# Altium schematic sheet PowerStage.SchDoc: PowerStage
size A2; Date: Not shown in title block; ApprovedBy: Not shown in title block; CheckedBy: Not shown in title block; Author: Not shown in title block; CompanyName: TEXAS INSTRUMENTS; DrawnBy: Hely Zhang; Engineer: Hely Zhang; Organization: Not shown in title block; Address1: Not shown in title block; Address2: Not shown in title block; Address3: Not shown in title block; Address4: Not shown in title block; DocumentNumber: 3; Revision: Use project parameter SCH_Rev; SheetNumber: 3; SheetTotal: 6; PageSetup: Record=PageOptions¦CenterHorizontal=True¦CenterVertical=True¦PrintScale=1.00¦XCorrection=1.00¦YCorrection=1.00¦PrintKind=0¦BorderSize=5000000¦LeftOffset=0¦BottomOffset=0¦Orientation=2¦PaperLength=1000¦PaperWidth=1000¦Scale=100¦PaperSource=15¦PrintQuality=600¦MediaType=1¦DitherType=10¦PaperKind=Letter¦PrintScaleMode=1
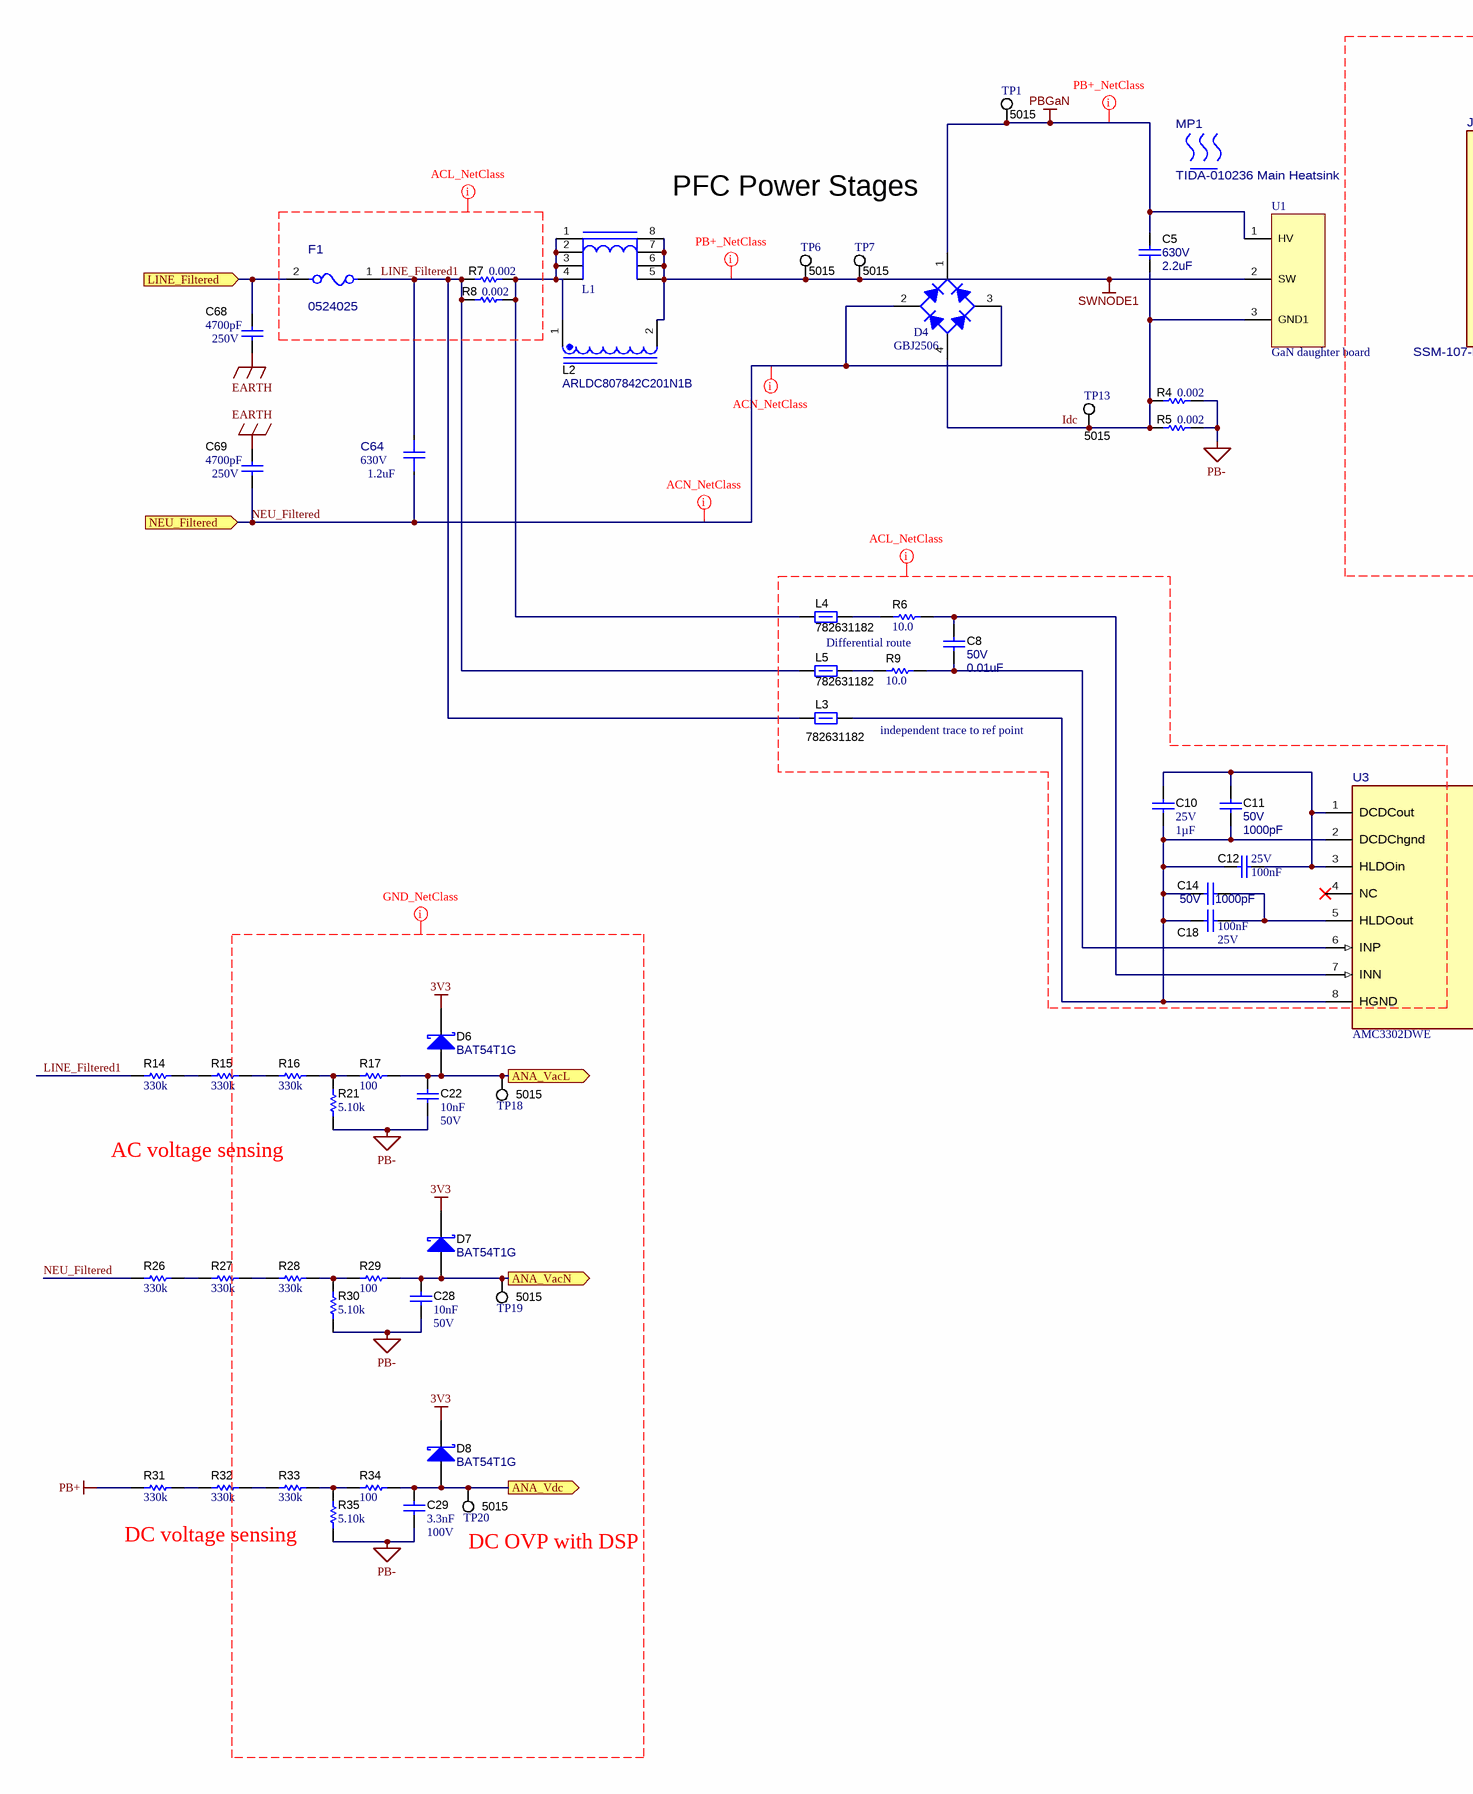
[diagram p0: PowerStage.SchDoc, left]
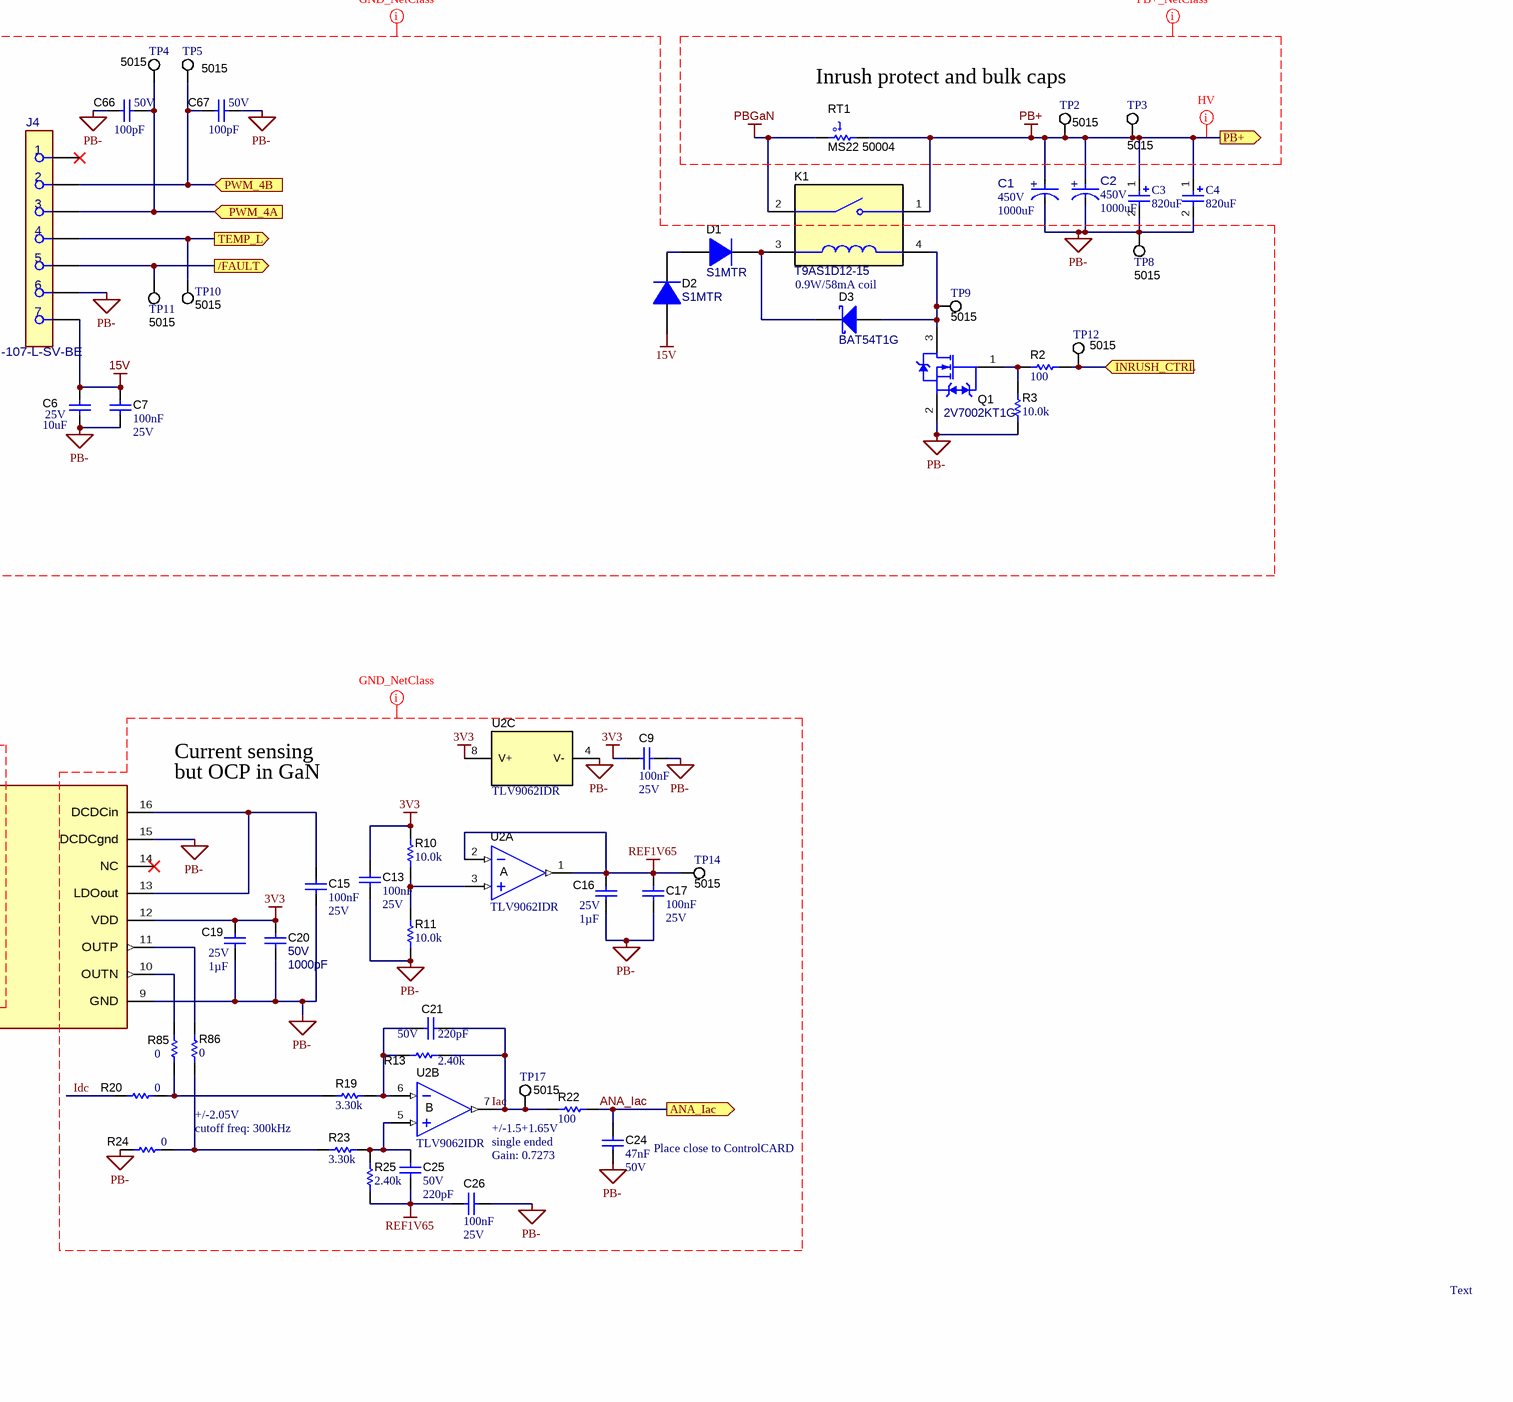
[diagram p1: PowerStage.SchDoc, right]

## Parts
C1  VDC_V: 450V  ValueDisplayed: 1000uF  [FP-S861021486045_RADIAL-MFG]  (hidden comment: S861021486045)
C2  VDC_V: 450V  ValueDisplayed: 1000uF  [FP-S861021486045_RADIAL-MFG]  (hidden comment: S861021486045)
C3  820uF  [Cap_35x60mm_Snap in]
C4  820uF  [Cap_35x60mm_Snap in]
C5  VDC_V: 630V  ValueDisplayed: 2.2uF  [B32924_24.5mm]  (hidden comment: ECWFG2J225)
C6  VDC_V: 25V  ValueDisplayed: 10uF  [1206_180]  (hidden comment: GRM31CR71E106KA12L)
C7  Cap_F: 100nF  VDC_V: 25V  [0603]  (hidden comment: GRM188R71E104KA01D)
C8  VDC_V: 50V  ValueDisplayed: 0.01uF  [0603]  (hidden comment: GRM188R71H103KA01D)
C9  Cap_F: 100nF  VDC_V: 25V  [0603]  (hidden comment: GRM188R71E104KA01D)
C10  VDC_V: 25V  Cap_F: 1µF  [0603]  (hidden comment: GRJ188R71E105KE11D)
C11  VDC_V: 50V  ValueDisplayed: 1000pF  [0603]  (hidden comment: GCJ188R71H102KA01D)
C12  Cap_F: 100nF  VDC_V: 25V  [0603]  (hidden comment: GRM188R71E104KA01D)
C13  Cap_F: 100nF  VDC_V: 25V  [0603]  (hidden comment: GRM188R71E104KA01D)
C14  VDC_V: 50V  ValueDisplayed: 1000pF  [0603]  (hidden comment: GCJ188R71H102KA01D)
C15  Cap_F: 100nF  VDC_V: 25V  [0603]  (hidden comment: GRM188R71E104KA01D)
C16  VDC_V: 25V  Cap_F: 1µF  [0603]  (hidden comment: GRJ188R71E105KE11D)
C17  Cap_F: 100nF  VDC_V: 25V  [0603]  (hidden comment: GRM188R71E104KA01D)
C18  Cap_F: 100nF  VDC_V: 25V  [0603]  (hidden comment: GRM188R71E104KA01D)
C19  VDC_V: 25V  Cap_F: 1µF  [0603]  (hidden comment: GRJ188R71E105KE11D)
C20  VDC_V: 50V  ValueDisplayed: 1000pF  [0603]  (hidden comment: GCJ188R71H102KA01D)
C21  VDC_V: 50V  ValueDisplayed: 220pF  [0603]  (hidden comment: GRM1885C1H221JA01D)
C22  Cap_F: 10nF  VDC_V: 50V  [0603]  (hidden comment: GRM188R71H103KA01D)
C24  Cap_F: 47nF  VDC_V: 50V  [0603]  (hidden comment: GRM188R71H473KA61D)
C25  VDC_V: 50V  ValueDisplayed: 220pF  [0603]  (hidden comment: GRM1885C1H221JA01D)
C26  Cap_F: 100nF  VDC_V: 25V  [0603]  (hidden comment: GRM188R71E104KA01D)
C28  Cap_F: 10nF  VDC_V: 50V  [0603]  (hidden comment: GRM188R71H103KA01D)
C29  Cap_F: 3.3nF  VDC_V: 100V  [0603]  (hidden comment: GRM188R72A332KA01D)
C64  VDC_V: 630V  ValueDisplayed: 1.2uF  [FP-890334027012CS_RADIAL-MFG]  (hidden comment: 890334027012CS)
C66  VDC_V: 50V  ValueDisplayed: 100pF  [0603]  (hidden comment: C0603C101J5GACTU)
C67  VDC_V: 50V  ValueDisplayed: 100pF  [0603]  (hidden comment: C0603C101J5GACTU)
C68  VDC_V: 250V  ValueDisplayed: 4700pF  [KY_1000x500x1300]  (hidden comment: DE2E3KY472MB3BM02F)
C69  VDC_V: 250V  ValueDisplayed: 4700pF  [KY_1000x500x1300]  (hidden comment: DE2E3KY472MB3BM02F)
D1  S1MTR  [SMA]
D2  S1MTR  [SMA]
D3  BAT54T1G  [SOD-123]
D4  PartNumber: GBJ2506  [Diode_Bridge_Horizontal_GBJ]  (hidden comment: Diode bridge 600VDC 25A GBJ)
D6  BAT54T1G  [SOD-123]
D7  BAT54T1G  [SOD-123]
D8  BAT54T1G  [SOD-123]
F1  0524025  [FP-0525025.MXEP_vm_AXIAL-MFG]
J4  SSM-107-L-SV-BE  [FP-SSM-107-L-SV-BE_HDR7-MFG]
K1  T9AS1D12-15  [Relay_T9AS1D12]
L1  1  [Boost_Inductor_250uH]  (value not drawn)
L2  ARLDC807842C201N1B  [ARLDC807842C201N1B]
L3  782631182  [0603]
L4  782631182  [0603]
L5  782631182  [0603]
MP1  TIDA-010236 Main Heatsink  [0-MFG]
Q1  2V7002KT1G  [SOT-23]
R2  ValueDisplayed: 100  [0603]  (hidden comment: RC0603FR-07100RL)
R3  ValueDisplayed: 10.0k  [0603]  (hidden comment: RC0603FR-0710KL)
R4  ValueDisplayed: 0.002  [2512]  (hidden comment: ERJ-M1WTF2M0U)
R5  ValueDisplayed: 0.002  [2512]  (hidden comment: ERJ-M1WTF2M0U)
R6  ValueDisplayed: 10.0  [0603]  (hidden comment: RC0603FR-0710RL)
R7  ValueDisplayed: 0.002  [2512]  (hidden comment: ERJ-M1WTF2M0U)
R8  ValueDisplayed: 0.002  [2512]  (hidden comment: ERJ-M1WTF2M0U)
R9  ValueDisplayed: 10.0  [0603]  (hidden comment: RC0603FR-0710RL)
R10  ValueDisplayed: 10.0k  [0603]  (hidden comment: RC0603FR-0710KL)
R11  ValueDisplayed: 10.0k  [0603]  (hidden comment: RC0603FR-0710KL)
R13  ValueDisplayed: 2.40k  [0603]  (hidden comment: RC0603FR-072K4L)
R14  ValueDisplayed: 330k  [1210]  (hidden comment: RC1210FR-07330KL)
R15  ValueDisplayed: 330k  [1210]  (hidden comment: RC1210FR-07330KL)
R16  ValueDisplayed: 330k  [1210]  (hidden comment: RC1210FR-07330KL)
R17  ValueDisplayed: 100  [0603]  (hidden comment: RC0603FR-07100RL)
R19  ValueDisplayed: 3.30k  [0603]  (hidden comment: RC0603FR-073K3L)
R20  ValueDisplayed: 0  [0603]  (hidden comment: RC0603JR-070RL)
R21  ValueDisplayed: 5.10k  [0603]  (hidden comment: RC0603FR-075K1L)
R22  ValueDisplayed: 100  [0603]  (hidden comment: RC0603FR-07100RL)
R23  ValueDisplayed: 3.30k  [0603]  (hidden comment: RC0603FR-073K3L)
R24  ValueDisplayed: 0  [0603]  (hidden comment: RC0603JR-070RL)
R25  ValueDisplayed: 2.40k  [0603]  (hidden comment: RC0603FR-072K4L)
R26  ValueDisplayed: 330k  [1210]  (hidden comment: RC1210FR-07330KL)
R27  ValueDisplayed: 330k  [1210]  (hidden comment: RC1210FR-07330KL)
R28  ValueDisplayed: 330k  [1210]  (hidden comment: RC1210FR-07330KL)
R29  ValueDisplayed: 100  [0603]  (hidden comment: RC0603FR-07100RL)
R30  ValueDisplayed: 5.10k  [0603]  (hidden comment: RC0603FR-075K1L)
R31  ValueDisplayed: 330k  [1210]  (hidden comment: RC1210FR-07330KL)
R32  ValueDisplayed: 330k  [1210]  (hidden comment: RC1210FR-07330KL)
R33  ValueDisplayed: 330k  [1210]  (hidden comment: RC1210FR-07330KL)
R34  ValueDisplayed: 100  [0603]  (hidden comment: RC0603FR-07100RL)
R35  ValueDisplayed: 5.10k  [0603]  (hidden comment: RC0603FR-075K1L)
R85  ValueDisplayed: 0  [0603]  (hidden comment: RC0603JR-070RL)
R86  ValueDisplayed: 0  [0603]  (hidden comment: RC0603JR-070RL)
RT1  MS22 50004  [MS2250004]
TP1  5015  [Testpoint_Keystone_Miniature]
TP2  5015  [Testpoint_Keystone_Miniature]
TP3  5015  [Testpoint_Keystone_Miniature]
TP4  5015  [Testpoint_Keystone_Miniature]
TP5  5015  [Testpoint_Keystone_Miniature]
TP6  5015  [Testpoint_Keystone_Miniature]
TP7  5015  [Testpoint_Keystone_Miniature]
TP8  5015  [Testpoint_Keystone_Miniature]
TP9  5015  [Testpoint_Keystone_Miniature]
TP10  5015  [Testpoint_Keystone_Miniature]
TP11  5015  [Testpoint_Keystone_Miniature]
TP12  5015  [Testpoint_Keystone_Miniature]
TP13  5015  [Testpoint_Keystone_Miniature]
TP14  5015  [Testpoint_Keystone_Miniature]
TP17  5015  [Testpoint_Keystone_Miniature]
TP18  5015  [Testpoint_Keystone_Miniature]
TP19  5015  [Testpoint_Keystone_Miniature]
TP20  5015  [Testpoint_Keystone_Miniature]
U1  GaN daughter board  [GaN Daughter board 3]
U2  TLV9062IDR  [D0008A_N]  (parts A,B,C of 3)
U3  AMC3302DWE  [DWE0016A-MFG]

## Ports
/FAULT (out), ANA_Iac (out), ANA_VacL (out), ANA_VacN (out), ANA_Vdc (out), INRUSH_CTRL (in), LINE_Filtered (in), NEU_Filtered (in), PB+ (out), PWM_4A (in), PWM_4B (in), TEMP_L (out)

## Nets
3V3: C9.1 C13.1 C19.1 C20.2 D6.1(K) D7.1(K) D8.1(K) R10.2 U2.8(V+) U3.12(VDD)
15V: C6.1 C7.1 D2.2(A) J4.7
EARTH: C68.2 C69.1
PB+: C1.2(ANODE) C2.2(ANODE) C3.1 C4.1 K1.1 R31.1 RT1.1 TP2.1 TP3.1 ; port PB+
PB-: C1.1(CATHODE) C2.1(CATHODE) C3.2 C4.2 C6.2 C7.2 C9.2 C13.2 C15.2 C16.2 C17.2 C19.2 C20.1 C22.2 C24.2 C26.2 C28.2 C29.2 C66.1 C67.1 J4.6 Q1.2(S) R3.1 R4.2 R5.2 R11.1 R21.1 R24.1 R30.1 R35.1 TP8.1 U2.4(V-) U3.9(GND) U3.15(DCDCgnd)
PBGaN: C5.1 D4.1(K) K1.2 RT1.2 TP1.1 U1.1(HV)
REF1V65: C16.1 C17.1 C25.2 C26.1 R25.1 TP14.1 U2.1(OUT) U2.2(IN-)
SWNODE1: L1.5 L1.6 L1.7 L1.8 L2.2 TP6.1 TP7.1 U1.2(SW)
/FAULT: J4.5 TP11.1 ; port /FAULT
ANA_Iac: C24.1 R22.2 ; port ANA_Iac
ANA_VacL: C22.1 D6.2(A) R17.2 TP18.1 ; port ANA_VacL
ANA_VacN: C28.1 D7.2(A) R29.2 TP19.1 ; port ANA_VacN
ANA_Vdc: C29.1 D8.2(A) R34.2 TP20.1 ; port ANA_Vdc
Idc: C5.2 D4.4(A) R4.1 R5.1 R20.1 TP13.1 U1.3(GND1)
INRUSH_CTRL: R2.2 TP12.1 ; port INRUSH_CTRL
LINE_Filtered: C68.1 F1.2 ; port LINE_Filtered
LINE_Filtered1: C64.2 F1.1 L3.2 L5.2 R7.1 R8.1 R14.1
NEU_Filtered: C64.1 C69.2 D4.2(C) D4.3(C) R26.1 ; port NEU_Filtered
PWM_4A: C66.2 J4.3 TP4.1 ; port PWM_4A
PWM_4B: C67.2 J4.2 TP5.1 ; port PWM_4B
TEMP_L: J4.4 TP10.1 ; port TEMP_L
NetC8_1: C8.1 R6.2 U3.7(INN)
NetC8_2: C8.2 R9.2 U3.6(INP)
NetC10_1: C10.1 C11.1 C12.2 U3.1(DCDCout) U3.3(HLDOin)
NetC10_2: C10.2 C11.2 C12.1 C14.1 C18.1 L3.1 U3.2(DCDChgnd) U3.8(HGND)
NetC14_2: C14.2 C18.2 U3.5(HLDOout)
NetC15_1: C15.1 U3.13(LDOout) U3.16(DCDCin)
NetC21_1: C21.1 R13.1 R22.1 TP17.1 U2.7(OUT)
NetC21_2: C21.2 R13.2 R19.2 U2.6(IN-)
NetC25_1: C25.1 R23.2 R25.2 U2.5(IN+)
NetD1_1: D1.1(K) D3.1(K) K1.3
NetD1_2: D1.2(A) D2.1(K)
NetD3_2: D3.2(A) K1.4 Q1.3(D) TP9.1
NetL1_1: L1.1 L1.2 L1.3 L1.4 L2.1 L4.2 R7.2 R8.2
NetL4_1: L4.1 R6.1
NetL5_1: L5.1 R9.1
NetQ1_1: Q1.1(G) R2.1 R3.2
NetR10_1: R10.1 R11.2 U2.3(IN+)
NetR14_2: R14.2 R15.1
NetR15_2: R15.2 R16.1
NetR16_2: R16.2 R17.1 R21.2
NetR19_1: R19.1 R20.2 R85.1
NetR23_1: R23.1 R24.2 R86.1
NetR26_2: R26.2 R27.1
NetR27_2: R27.2 R28.1
NetR28_2: R28.2 R29.1 R30.2
NetR31_2: R31.2 R32.1
NetR32_2: R32.2 R33.1
NetR33_2: R33.2 R34.1 R35.2
NetR85_2: R85.2 U3.10(OUTN)
NetR86_2: R86.2 U3.11(OUTP)

Not connected (* = marked no-connect by the designer): J4 1*; U3 4(NC)* 14(NC)*

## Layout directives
net class HV: PB+
net class PB+_NetClass: PB+, PBGaN, SWNODE1
net class GND_NetClass: 3V3, 15V, ANA_Iac, Iac, Idc, PB+, PB-, PBGaN, REF1V65
net class ACN_NetClass: NEU_Filtered
net class ACL_NetClass: (no net found under the mark), LINE_Filtered1

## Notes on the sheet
- Inrush protect and bulk caps
- PFC Power Stages
- 0.9W/58mA coil
- Differential route
- independent trace to ref point
- Current sensing
- but OCP in GaN
- +/-2.05V
- cutoff freq: 300kHz
- +/-1.5+1.65V
- single ended
- (near R21) AC voltage sensing
- Gain: 0.7273
- (near C24) Place close to ControlCARD
- Text
- (near R35) DC voltage sensing
- (near TP20) DC OVP with DSP
- Labels drawn without touching a wire or pin: Iac

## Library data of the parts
C1 C2 = CMP-0094965-1: WCAP-AIG5 Aluminum Electrolytic Capacitors 1000uF ±20% 450VDC; Manufacturer: Wurth; AEC Qualified: No; Value: 1mF; Esr: 0.2; Life: 2000Hours; IRMS_A: 3.2A; SizeZ_mm: 62mm; Leakage Current: 2012uA
C3 C4 = ECAP1
C5 = CMP-0012436-3: CAP, Film, 2.2 uF, 630 V, +/- 20%, TH; Manufacturer: Panasonic; Polarized: N; SizeAreaWB_mm2: 536; Value1: Unknown; Value: 2.2uF; TaMax_C: 110°C; SizeZ_mm: 24.5; SizeX_mm: 12; SizeY_mm: 31.5; SizeArea_mm2: 441; Cap_F: 2.2µF; AEC Category: Q200
C6 = CMP-0008965-2: CAP, CERM, 10 uF, 25 V, +/- 10%, X7R, 1206; Manufacturer: MuRata; TaMin_C: -55°C; Polarized: N; SizeAreaWB_mm2: 10.92; Value1: Unknown; U/M: EA; Value: 10uF; TaMax_C: 125°C; SizeZ_mm: 1.8; SizeX_mm: 3.2; SizeY_mm: 1.6; Cap_Case: 2220; SizeArea_mm2: 5.12; Cap_F: 10µF; AEC Category: Q200
C7 C9 C12 C13 C15 C17 C18 C26 = CMP-0007404-5: CAP, CERM, 0.1 uF, 25 V, +/- 10%, X7R, 0603; Manufacturer: MuRata; ValueDisplayed: 0.1uF; SizeAreaWB_mm2: 4.68; MFG_Status: TI_Obsolete; SizeZ_mm: 1; SizeY_mm: 0.8; Value: 0.1uF; AEC Category: Q200; Value1: Unknown; SizeX_mm: 1.6; TaMin_C: -55°C; Polarized: N; TaMax_C: 125°C; SizeArea_mm2: 1.28; U/M: EA
C8 = CMP-0007433-4: CAP, CERM, 0.01 uF, 50 V, +/- 10%, X7R, 0603; Manufacturer: MuRata; TaMin_C: -55°C; Polarized: N; SizeAreaWB_mm2: 4.68; Value1: Unknown; U/M: EA; Value: 0.01uF; TaMax_C: 125°C; SizeZ_mm: 1; SizeX_mm: 1.6; SizeY_mm: 0.8; SizeArea_mm2: 1.28; Cap_F: 10nF; AEC Category: Q200
C10 C16 C19 = CMP-0079720-2: CAP, CERM, 1 µF, 25 V,+/- 10%, X7R, 0603; Manufacturer: MuRata; AEC Category: Q200; TaMin_C: -55°C; AEC Qualified: N; SizeAreaWB_mm2: 4.68; SizeArea_mm2: 1.28; Value: 1uF; SizeZ_mm: 1; SizeX_mm: 1.6; U/M: EA; MFG_Status: TI_Obsolete; SizeY_mm: 0.8; TaMax_C: 125°C
C11 C14 C20 = CMP-0007432-5: CAP, CERM, 1000 pF, 50 V, +/- 10%, X7R, 0603; Manufacturer: MuRata; TaMin_C: -55°C; Polarized: N; SizeAreaWB_mm2: 4.68; Value1: Unknown; U/M: EA; Value: 1000pF; TaMax_C: 125°C; SizeZ_mm: 1; SizeX_mm: 1.6; SizeY_mm: 0.8; SizeArea_mm2: 1.28; Cap_F: 1nF; AEC Category: Q200
C21 C25 = CMP-0007197-4: CAP, CERM, 220 pF, 50 V, +/- 5%, C0G/NP0, 0603; Manufacturer: MuRata; TaMin_C: -55°C; Polarized: N; SizeAreaWB_mm2: 4.68; Value1: Unknown; U/M: EA; Value: 220pF; TaMax_C: 125°C; SizeZ_mm: 1; SizeX_mm: 1.6; SizeY_mm: 0.8; SizeArea_mm2: 1.28; AEC Category: Q200
C22 C28 = CMP-0007433-4: CAP, CERM, 0.01 uF, 50 V, +/- 10%, X7R, 0603; Manufacturer: MuRata; TaMin_C: -55°C; Polarized: N; SizeAreaWB_mm2: 4.68; Value1: Unknown; U/M: EA; Value: 0.01uF; TaMax_C: 125°C; SizeZ_mm: 1; SizeX_mm: 1.6; SizeY_mm: 0.8; SizeArea_mm2: 1.28; AEC Category: Q200
C24 = CMP-0007457-4: CAP, CERM, 0.047 uF, 50 V, +/- 10%, X7R, 0603; Manufacturer: MuRata; TaMin_C: -55°C; Polarized: N; SizeAreaWB_mm2: 4.68; Value1: Unknown; U/M: EA; TaMax_C: 125°C; SizeZ_mm: 1; SizeX_mm: 1.6; SizeY_mm: 0.8; SizeArea_mm2: 1.28; AEC Category: Q200
C29 = CMP-0007479-4: CAP, CERM, 3300 pF, 100 V, +/- 10%, X7R, 0603; Manufacturer: MuRata; TaMin_C: -55°C; Polarized: N; SizeAreaWB_mm2: 4.68; Value1: Unknown; U/M: EA; Value: 3300pF; TaMax_C: 125°C; SizeZ_mm: 1; SizeX_mm: 1.6; SizeY_mm: 0.8; SizeArea_mm2: 1.28; AEC Category: Q200
C64 = CMP-0090546-1: 1.2µF Film Capacitor 310V  Polypropylene (PP), Metallized Radial; Manufacturer: Wurth Electronics; AEC Qualified: No; Tolerance_%: 10%; SizeZ_mm: 22.5mm
C66 C67 = CMP-0006841-4: CAP, CERM, 100 pF, 50 V, +/- 5%, C0G/NP0, 0603; Manufacturer: Kemet; TaMin_C: -55°C; Polarized: N; SizeAreaWB_mm2: 4.68; Value1: Unknown; U/M: EA; Value: 100pF; TaMax_C: 125°C; SizeZ_mm: 1; SizeX_mm: 1.6; SizeY_mm: 0.8; SizeArea_mm2: 1.28; AEC Category: Q200
C68 C69 = CMP-0009611-1: CAP, CERM, 4700 pF, 250 V, +/- 20%, E, 10x5x13mm; Manufacturer: MuRata; TaMin_C: -40°C; Polarized: N; SizeAreaWB_mm2: 84; Value1: Unknown; U/M: EA; Value: 4700pF; TaMax_C: 125°C; SizeZ_mm: 13; SizeX_mm: 10; SizeY_mm: 5; SizeArea_mm2: 50; Cap_F: 4.7nF; AEC Category: Q200
D1 D2 = CMP-0078438-2: Diode, Standard Recovery Rectifier, 1000 V, 1 A, SMA; Manufacturer: SMC Diode Solutions; Vf_V: 1.1V; TJmax_C: 175°C; SizeZ_mm: 2.87; SizeY_mm: 2.92; AEC Qualified: N; Vr_V: 1kV; Value1: 1A; SizeAreaWB_mm2: 37.3428; SizeArea_mm2: 16.3228; Value: 1000V; AEC Category: Q101; SizeX_mm: 5.59
D3 D6-D8 = CMP-0028457-2: Diode, Schottky, 30 V, 0.2 A, SOD-123; Manufacturer: ON Semiconductor; SizeArea_mm2: 6.545; Io_A: 200mA; SizeX_mm: 3.85; Value1: 0.2A; SizeY_mm: 1.7; AEC Category: Q101; Vf_V: 800mV; TJmax_C: 125°C; Green_Lifecycle: Not Set; RJC_CperW: 174; Value: 30V; Value2: 0.8V; SizeAreaWB_mm2: 13.095; Green_REACh: Incomplete; SizeZ_mm: 1.35
D4 = Diode bridge: Diode Bridge recotifier 1 phase 600V 25A TH; Manufacturer: Diodes Inc.; Vr_V: 1.05V
F1 = CMP-4956-0000-1: FUSE CERM 25A 250VAC 125VDC 3AB; Part Number: 0324025.MXP; Manufacturer: Littelfuse; AEC Grade: NA; Fuse Interrupt Dc Current: 10000A; AEC Qualified: No; VDC_V: 450V; Res_ohm: 3.8mΩ; MeltingTyp: 320A2Sec; Interrupt_DC: 10kA
J4 = CMP-0095208-1: Manufacturer: Samtec; Conn Orientation: Vertical; Voltage_V: 572V; Current_A: 5.2A; Is Female: yes; AEC Qualified: No; Conn Gender: Female; SizeZ_mm: 7.541mm; ContactFinish: Gold,Nickel; DUT-Pitch_mm: 2.54mm; Row_Count: 1
K1 = CMP-0078608-2: Relay, SPST-NO (1 Form A), 30 A, 15 V, TH; Manufacturer: TE Connectivity; Contact Rating_A: 30A; Turn On Voltage (Max)_VDC: 11.25V; Coil Power_W: 1W; Coil Resistance_ohm: 225; SizeAreaWB_mm2: 1015.6293; Time Operate (s): 15ms; Coil Current_A: 66.7mA; SizeZ_mm: 20.4; SizeX_mm: 32.51; SizeY_mm: 27.43; SizeArea_mm2: 891.7493; Turn Off Voltage (Min)_VDC: 1.5V; Coil Type: Non Latching; Coil Voltage_VDC: 15V
L1 = Boost_Inductor_250uH: Inductor 265uH 26A vertical
L2 = CHOKE_PQ35: PFC CHOKE 480uH 33A; Manufacturer: Sunlord; Green_REACh: Incomplete; CompType: Transformer; Green_Lifecycle: Not Set; SizeX_mm: 30; SizeY_mm: 22; SizeZ_mm: 34; Value: 300uH
L3-L5 = CMP-0003277-1: Ferrite Bead, 1800 ohm @ 100 MHz, 0.2 A, 0603; Manufacturer: Wurth Elektronik; Ztyp@1GHz_Ohm: 217.379; ZTyp@100MHz_Ohm: 1.8k; SizeAreaWB_mm2: 4.68; DCR_ohm: 0.75; Value1: 0.75 ohm; Imax_A: 200mA; SizeZ_mm: 1; SizeX_mm: 1.6; SizeY_mm: 0.8; Value2: 0.2A; SizeArea_mm2: 1.28
MP1 = CMP-0097532-1: Main Heatsink; Manufacturer: Texas Instruments; SizeZ_mm: 17mm
Q1 = CMP-0000777-1: MOSFET, N-CH, 60 V, 0.32 A, AEC-Q101, SOT-23; Alternate Manufacturer: None; Manufacturer: ON Semiconductor; SizeZ_mm: 1.1; ChType: N; Value2: 0.7 nC; Value1: 2; VdsMax_V: 60V; SizeX_mm: 2.5; SizeY_mm: 3; Vgs_V: 20V; AEC Qualified: Y; Value: 60V; SizeArea_mm2: 7.5; AEC Category: Q101; IdsMax_A: 320mA; SizeAreaWB_mm2: 14; U/M: EA; QgTyp_nC: 0.7
R2 R17 R22 R29 R34 = CMP-0022736-4: RES, 100, 1%, 0.1 W, 0603; Manufacturer: Yageo; Power_W: 100mW; TempCo: 100 ppm/C; Value_Code: 100R; Value: 100; EIA_Code: E96; SizeX_mm: 1.6; SizeY_mm: 0.8; SizeZ_mm: 1; Value2: 0.1W; SizeArea_mm2: 1.28; AEC Qualified: N; VDC_V: 75V; AEC Category: Q200; SizeAreaWB_mm2: 4.68
R3 R10 R11 = CMP-0022746-5: RES, 10.0 k, 1%, 0.1 W, 0603; Manufacturer: Yageo; Power_W: 100mW; TempCo: 100 ppm/C; Value_Code: 10k0; Value: 10.0k; EIA_Code: E96; Res_ohm: 10k; SizeX_mm: 1.6; SizeY_mm: 0.8; SizeZ_mm: 1; Value2: 0.1W; SizeArea_mm2: 1.28; AEC Qualified: N; VDC_V: 75V; AEC Category: Q200; SizeAreaWB_mm2: 4.68
R4 R5 R7 R8 = CMP-0015819-2: RES, 0.002, 1%, 1 W, 2512; Manufacturer: Panasonic; Power_W: 1W; TempCo: ppm/C; Value_Code: 2L000; U/M: EA; Value: 0.002; Res_ohm: 2m; SizeX_mm: 6.3; SizeY_mm: 3.2; SizeZ_mm: 0.71; SizeArea_mm2: 20.16; AEC Category: Q200
R6 R9 = CMP-0022751-4: RES, 10.0, 1%, 0.1 W, 0603; Manufacturer: Yageo; Power_W: 100mW; TempCo: 100 ppm/C; Value_Code: 10R0; Value: 10.0; EIA_Code: E96; Res_ohm: 10; SizeX_mm: 1.6; SizeY_mm: 0.8; SizeZ_mm: 1; Value2: 0.1W; SizeArea_mm2: 1.28; AEC Qualified: N; VDC_V: 75V; AEC Category: Q200; SizeAreaWB_mm2: 4.68
R13 R25 = CMP-0022991-5: RES, 2.40 k, 1%, 0.1 W, 0603; Manufacturer: Yageo; Power_W: 100mW; TempCo: 100 ppm/C; Value_Code: 2k40; Value: 2.40k; Res_ohm: 2.4k; SizeX_mm: 1.6; SizeY_mm: 0.8; SizeZ_mm: 1; Value2: 0.1W; SizeArea_mm2: 1.28; AEC Qualified: N; VDC_V: 75V; AEC Category: Q200; SizeAreaWB_mm2: 4.68
R14-R16 R26-R28 R31-R33 = CMP-0083082-1: RES, 330 k, 1%, 0.5 W, 1210; Manufacturer: Yageo; Power_W: 500mW; TempCo: 100 ppm/C; SizeAreaWB_mm2: 14.7; Value: 330k; SizeX_mm: 3.2; SizeY_mm: 2.5; SizeZ_mm: 1.35; Value2: 0.5W; SizeArea_mm2: 8; AEC Qualified: N; VDC_V: 200V; AEC Category: Q200
R19 R23 = CMP-0023081-5: RES, 3.30 k, 1%, 0.1 W, 0603; Manufacturer: Yageo; Power_W: 100mW; TempCo: 100 ppm/C; Value_Code: 3k30; Value: 3.30k; Res_ohm: 3.3k; SizeX_mm: 1.6; SizeY_mm: 0.8; SizeZ_mm: 1; Value2: 0.1W; SizeArea_mm2: 1.28; AEC Qualified: N; VDC_V: 75V; AEC Category: Q200; SizeAreaWB_mm2: 4.68
R20 R24 R85 R86 = CMP-0025885-5: RES, 0, 5%, 0.1 W, 0603; Manufacturer: Yageo; Power_W: 100mW; TempCo: 200 ppm/C; Value_Code: 0000; Value: 0; EIA_Code: E24; SizeX_mm: 1.6; SizeZ_mm: 1; Value2: 0.1W; SizeArea_mm2: 1.28; AEC Qualified: N; VDC_V: 75V; AEC Category: Q200; SizeY_mm: 0.8; SizeAreaWB_mm2: 4.68
R21 R30 R35 = CMP-0023198-5: RES, 5.10 k, 1%, 0.1 W, 0603; Manufacturer: Yageo; Power_W: 100mW; TempCo: 100 ppm/C; Value_Code: 5k10; Value: 5.10k; Res_ohm: 5.1k; SizeX_mm: 1.6; SizeY_mm: 0.8; SizeZ_mm: 1; Value2: 0.1W; SizeArea_mm2: 1.28; AEC Qualified: N; VDC_V: 75V; AEC Category: Q200; SizeAreaWB_mm2: 4.68
RT1 = B59751B0120A070: Thermistor PTC, 50 ohm, 25%, D23 x T10mm, P7.8mm; Manufacturer: Ametherm; CompType: ThermistorNTC; Value: 50; Tolerance_%: 25; TaMin_C: -40; TaMax_C: 125; U/M: EA
TP1-TP14 TP17-TP20 = CMP-0055152-1: Test Point, Miniature, SMT; Manufacturer: Keystone; CNHeader: FALSE; Green_Lifecycle: Active; Green_REACh: Passed; CT: TRUE
U1 = GaN_Daughter_Board_2
U2 = CMP-0013007-4: 10-MHz, Low-Noise, RRIO, CMOS Operational Amplifier for Cost-Sensitive Systems, D0008A (SOIC-8); Manufacturer: Texas Instruments; SizeX_mm: 4.9; SizeY_mm: 6.2; CompType: IC; SizeZ_mm: 1.75; SizeArea_mm2: 30.38; SizeAreaWB_mm2: 56.58; AEC Category: Q200; AEC Qualified: N; Rating: Catalog
U3 = CMP-0089607-3: Precision, ±250-mV Input, Reinforced Isolated Amplifier With Integrated DC/DC Converter; Manufacturer: Texas Instruments; AEC Category: Q200; Nominal Supply Current: 27.5-28.5mA; TaMin_C: -40°C; CompType: IC; Max Supply Voltage: 5.5V; Min Supply Voltage: 3V; AEC Qualified: No; TJmax_C: +150°C; SizeZ_mm: 2.65mm; Standoff Height: 0.1mm; TaMax_C: +125°C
